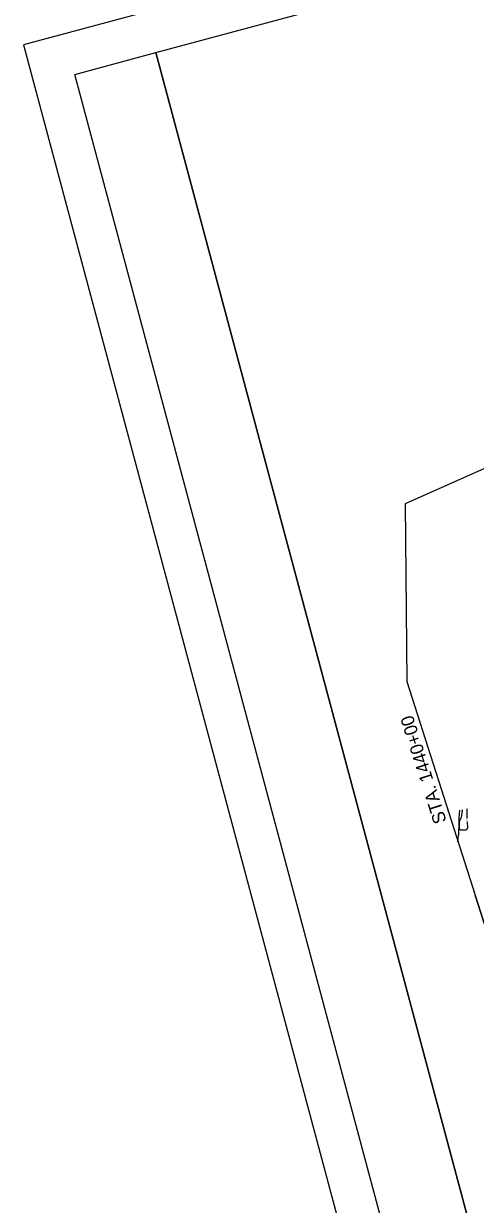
# Model space of a CAD drawing. Extents: x -361782338 to 28259792, y -263199453 to 8342113.
# Drawn here: x 1399169 to 1400786, y 575494 to 579715 of the extents above; entities that cross this region are included whole.
import ezdxf

# ---------------------------------------------------------------- set-up
doc = ezdxf.new("R2010")
doc.units = 0
for name, color, linetype in [('DT_X_Contour_Minor', 7, 'Continuous'), ('DT_X_Terrain_Ground_Line', 7, 'Continuous'), ('Level 19', 7, 'Continuous'), ('SC_Scratch1', 7, 'Continuous'), ('SH_Border', 7, 'Continuous'), ('SH_Cut_Line', 7, 'Continuous')]:
    doc.layers.add(name, color=color, linetype=linetype)

msp = doc.modelspace()

# ---------------------------------------------------------------- linework, layer by layer
at = {"layer": 'DT_X_Contour_Minor'}
for points in [[(1400729, 576902.5), (1400727.3, 576874.6), (1400726.7, 576855.6), (1400725.4, 576820), (1400725.1, 576813.5)], [(1400756.2, 576860.8), (1400757.4, 576839.8), (1400756.5, 576836.1), (1400755.1, 576833.5), (1400752.4, 576831.6), (1400748.3, 576831), (1400734.5, 576832), (1400731.6, 576833.3), (1400729.8, 576837.7), (1400729.1, 576846.2), (1400729.4, 576856.5), (1400730.7, 576865.6), (1400732.6, 576871.4), (1400734.8, 576875.1), (1400736.8, 576878.9), (1400738.1, 576884.5), (1400738.9, 576891.4), (1400739.5, 576904.4)], [(1400755.9, 576907.4), (1400755.4, 576879.2), (1400755.6, 576872.8)], [(1400723.9, 576789.8), (1400723.9, 576790.1), (1400725.1, 576813.5)]]:
    msp.add_lwpolyline(points, dxfattribs=at)
at = {"layer": 'DT_X_Terrain_Ground_Line'}
for p in [(1400540.5, 577362.5), (1401030.8, 575831.8)]:
    msp.add_line(p, (1400785.1, 576598.8), dxfattribs=at)
at = {"layer": 'SC_Scratch1'}
msp.add_lwpolyline([(1400540.5, 577362.5), (1401030.8, 575831.8), (1401384.6, 574706.6), (1408690.6, 576642.8), (1409300.2, 577585.4), (1408847.3, 578980.3), (1403882.9, 579488), (1400534.4, 577997.6)], close=True, dxfattribs=at)
at = {"layer": 'SH_Border'}
for points in [[(1399642.8, 579611), (1408915.7, 582095.7), (1410546.3, 576010.3), (1401273.4, 573525.7)], [(1399353, 579533.3), (1399642.8, 579611), (1401273.4, 573525.7), (1400983.6, 573448)]]:
    msp.add_lwpolyline(points, close=True, dxfattribs=at)
at = {"layer": 'SH_Cut_Line'}
msp.add_lwpolyline([(1400877.5, 573264.3), (1410730, 575904.3), (1409021.8, 582279.4), (1399169.3, 579639.4)], close=True, dxfattribs=at)

# ---------------------------------------------------------------- texts
at = {"layer": 'DT_X_Terrain_Ground_Line'}
msp.add_text('STA. 1440+00', height=46.8, rotation=107.7616, dxfattribs=at).set_placement((1400683.8, 576863.2))
at = {"layer": 'Level 19'}
msp.add_text('716', height=4, rotation=273.341, dxfattribs=at).set_placement((1400753.6, 576872.1))

doc.saveas('drawing.dxf')
